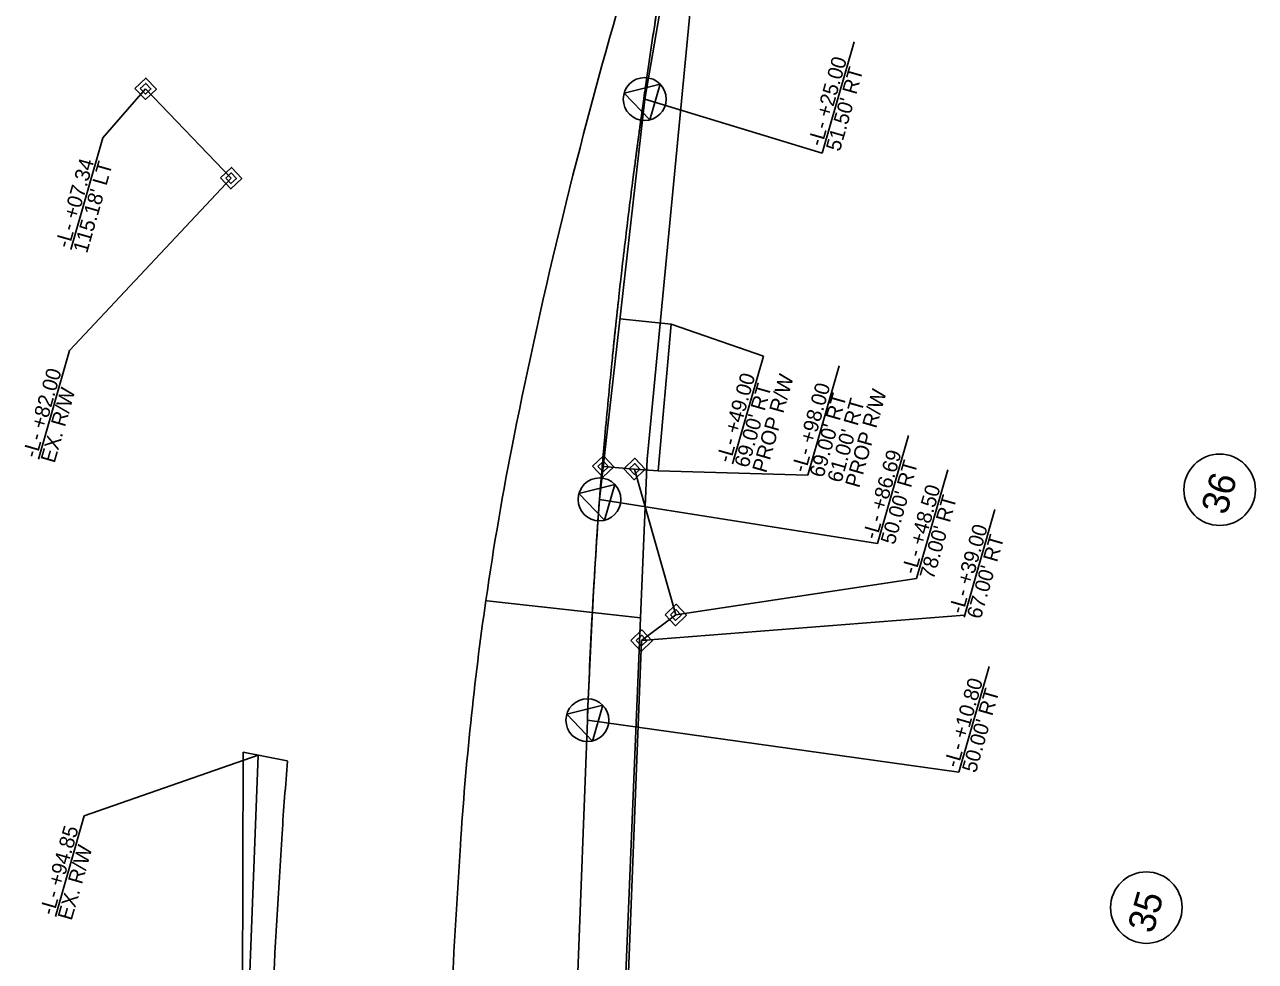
# Model space of a CAD drawing. Extents: x 2097272 to 2098144, y 685104 to 689282.
# Drawn here: x 2097646.2 to 2098059.6, y 688445.5 to 688760 of the extents above; entities that cross this region are included whole.
import ezdxf

# ---------------------------------------------------------------- set-up
doc = ezdxf.new("R2010")
doc.units = 0
for name, color, linetype in [('Prop Easement Construction', 7, 'Continuous'), ('Prop Easement Construction Station Offsets', 7, 'Continuous'), ('Prop Easement Permanent Utility', 7, 'Continuous'), ('Prop Easement Permanent Utility Station Offsets', 7, 'Continuous'), ('Prop Parcel Number CELL', 7, 'Continuous'), ('Prop ROW Marker CELL', 7, 'Continuous'), ('Prop ROW Permanent Easement CELL', 7, 'Continuous'), ('Prop ROW RW Lines', 7, 'Continuous'), ('Prop ROW Station Offsets', 7, 'Continuous'), ('Scratch_Level_3', 7, 'Continuous'), ('Scratch_Level_6', 7, 'Continuous')]:
    doc.layers.add(name, color=color, linetype=linetype)

msp = doc.modelspace()

# ---------------------------------------------------------------- linework, layer by layer
at = {"layer": 'Prop Easement Construction'}
for p, q in [((2097863.36, 688659.46), (2097846.12, 688661.16)), ((2097859.04, 688610.18), (2097863.36, 688659.46)), ((2097859.04, 688610.18), (2097851.06, 688610.79)), ((2097719.27, 688373.62), (2097724.68, 688514.75))]:
    msp.add_line(p, q, dxfattribs=at)
at = {"layer": 'Prop Easement Construction Station Offsets'}
for p, q in [((2097894.32, 688648.68), (2097863.36, 688659.46)), ((2097894.32, 688648.68), (2097883.97, 688612.54)), ((2097666.26, 688494.4), (2097724.68, 688514.75)), ((2097656.57, 688460.53), (2097666.26, 688494.4))]:
    msp.add_line(p, q, dxfattribs=at)
at = {"layer": 'Prop Easement Permanent Utility'}
for p, q in [((2097715.56, 688708.41), (2097686.86, 688738.44)), ((2097715.61, 688708.41), (2097715.5, 688708.42)), ((2097851.06, 688610.79), (2097840.52, 688611.6)), ((2097864.89, 688561.78), (2097851.06, 688610.79)), ((2097853.42, 688553.17), (2097864.89, 688561.78)), ((2097846.96, 688389.12), (2097853.42, 688553.17))]:
    msp.add_line(p, q, dxfattribs=at)
at = {"layer": 'Prop Easement Permanent Utility Station Offsets'}
for p, q in [((2097672.48, 688721.94), (2097686.86, 688738.44)), ((2097661.77, 688684.52), (2097672.48, 688721.94)), ((2097661.32, 688650.61), (2097715.56, 688708.41)), ((2097650.86, 688614.08), (2097661.32, 688650.61)), ((2097919.8, 688645.37), (2097909.3, 688608.7)), ((2097909.3, 688608.7), (2097859.04, 688610.18)), ((2097956.22, 688610.51), (2097945.76, 688573.98)), ((2097972.08, 688597.22), (2097961.73, 688561.08)), ((2097945.76, 688573.98), (2097864.89, 688561.78)), ((2097961.92, 688561.71), (2097853.42, 688553.17))]:
    msp.add_line(p, q, dxfattribs=at)
at = {"layer": 'Prop Parcel Number CELL'}
for centre in [(2098047.57, 688603.82), (2098022.94, 688463.54)]:
    msp.add_circle(centre, 12, dxfattribs=at)
at = {"layer": 'Prop ROW Marker CELL'}
for p, q in [((2097686.86, 688738.44), (2097686.86, 688738.44)), ((2097854.46, 688734.99), (2097854.46, 688734.99)), ((2097715.56, 688708.41), (2097715.56, 688708.41)), ((2097840.52, 688611.6), (2097840.52, 688611.6)), ((2097851.06, 688610.79), (2097851.06, 688610.79)), ((2097839.28, 688600.59), (2097839.28, 688600.59)), ((2097864.89, 688561.78), (2097864.89, 688561.78)), ((2097853.42, 688553.17), (2097853.42, 688553.17)), ((2097835.21, 688526.47), (2097835.21, 688526.47))]:
    msp.add_line(p, q, dxfattribs=at)
for points in [[(2097856.2, 688727.99), (2097847.54, 688736.97), (2097859.64, 688740)], [(2097841.02, 688593.59), (2097832.36, 688602.58), (2097844.46, 688605.61)], [(2097836.95, 688519.47), (2097828.29, 688528.45), (2097840.39, 688531.49)]]:
    msp.add_lwpolyline(points, close=True, dxfattribs=at)
for centre in [(2097854.46, 688734.99), (2097839.28, 688600.59), (2097835.21, 688526.47)]:
    msp.add_circle(centre, 7.2, dxfattribs=at)
at = {"layer": 'Prop ROW Permanent Easement CELL'}
for points in [[(2097683.26, 688738.54), (2097686.97, 688742.04), (2097690.46, 688738.33), (2097686.76, 688734.84)], [(2097685.06, 688738.49), (2097686.91, 688740.24), (2097688.66, 688738.38), (2097686.81, 688736.64)], [(2097711.96, 688708.52), (2097715.67, 688712.01), (2097719.16, 688708.31), (2097715.46, 688704.81)], [(2097713.76, 688708.47), (2097715.62, 688710.21), (2097717.36, 688708.36), (2097715.51, 688706.61)], [(2097836.92, 688611.7), (2097840.63, 688615.19), (2097844.12, 688611.49), (2097840.42, 688608)], [(2097838.72, 688611.65), (2097840.58, 688613.4), (2097842.32, 688611.54), (2097840.47, 688609.8)], [(2097847.47, 688610.9), (2097851.17, 688614.39), (2097854.66, 688610.69), (2097850.96, 688607.19)], [(2097849.26, 688610.84), (2097851.12, 688612.59), (2097852.86, 688610.74), (2097851.01, 688608.99)], [(2097861.29, 688561.88), (2097864.99, 688565.38), (2097868.48, 688561.67), (2097864.78, 688558.18)], [(2097863.09, 688561.83), (2097864.94, 688563.58), (2097866.68, 688561.73), (2097864.83, 688559.98)], [(2097849.82, 688553.27), (2097853.52, 688556.77), (2097857.01, 688553.06), (2097853.31, 688549.57)], [(2097851.62, 688553.22), (2097853.47, 688554.97), (2097855.22, 688553.12), (2097853.36, 688551.37)]]:
    msp.add_lwpolyline(points, close=True, dxfattribs=at)
at = {"layer": 'Prop ROW RW Lines'}
for p, q in [((2097854.46, 688734.99), (2097881.38, 688888.89)), ((2097839.28, 688600.59), (2097854.46, 688734.99)), ((2097823.42, 688219.05), (2097835.21, 688526.47))]:
    msp.add_line(p, q, dxfattribs=at)
msp.add_arc((2100083.56, 688440.25), 2250, 175.9133, 177.8037, dxfattribs=at)
at = {"layer": 'Prop ROW Station Offsets'}
for p, q in [((2097924.77, 688754.2), (2097914.07, 688716.83)), ((2097914.07, 688716.83), (2097854.46, 688734.99)), ((2097943.1, 688622.08), (2097932.7, 688585.75)), ((2097932.7, 688585.75), (2097839.28, 688600.59)), ((2097970.13, 688544.45), (2097960, 688509.06)), ((2097960, 688509.06), (2097835.21, 688526.47))]:
    msp.add_line(p, q, dxfattribs=at)
at = {"layer": 'Scratch_Level_3'}
for p, q in [((2097801.12, 688566.59), (2097801.56, 688566.55)), ((2097801.56, 688566.55), (2097801.12, 688566.59)), ((2097801.56, 688566.55), (2097836.89, 688562.64)), ((2097836.89, 688562.64), (2097801.56, 688566.55)), ((2097829.17, 688369.06), (2097835.21, 688526.47))]:
    msp.add_line(p, q, dxfattribs=at)
msp.add_lwpolyline([(2097839.28, 688600.59), (2097839.28, 688600.59)], dxfattribs=at)
for centre, radius, start, end in [((2099533.7, 688278.93), 1756.88, 163.79986, 168.76087), ((2098839.67, 688416.84), 1049.29, 168.76087, 171.79497), ((2100083.56, 688440.25), 2250, 175.9133, 176.88183), ((2100083.56, 688440.25), 2250, 175.913298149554, 175.91330221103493), ((2098839.67, 688416.84), 1049.29, 171.79497, 176.30351), ((2100083.56, 688440.25), 2250, 176.88183, 177.8037), ((2101879.05, 688220.48), 4095, 176.30351, 177.90917)]:
    msp.add_arc(centre, radius, start, end, dxfattribs=at)
for points, degree in [([(2097852.36, 688722), (2097852.38, 688722.16), (2097852.4, 688722.32), (2097852.45, 688722.63), (2097852.47, 688722.79), (2097852.51, 688723.1), (2097852.53, 688723.26), (2097852.56, 688723.46), (2097852.56, 688723.5), (2097852.58, 688723.58), (2097852.58, 688723.62), (2097852.6, 688723.74), (2097852.61, 688723.82), (2097852.7, 688724.53), (2097852.79, 688725.16), (2097853.05, 688727.05), (2097853.22, 688728.31), (2097853.75, 688732.09), (2097854.81, 688739.65), (2097856.65, 688752.25), (2097858.57, 688764.83), (2097859.76, 688772.38), (2097860.36, 688776.15), (2097860.56, 688777.41), (2097860.86, 688779.29), (2097860.97, 688779.92), (2097861.08, 688780.63), (2097861.09, 688780.71), (2097861.11, 688780.8), (2097861.11, 688780.82), (2097861.12, 688780.86), (2097861.12, 688780.88), (2097861.13, 688780.94), (2097861.14, 688780.98), (2097861.17, 688781.18), (2097861.2, 688781.33), (2097861.25, 688781.65), (2097861.27, 688781.81), (2097861.32, 688782.12), (2097861.35, 688782.28), (2097861.38, 688782.44)], 3), ([(2097844.99, 688661.33), (2097845.01, 688661.49), (2097845.02, 688661.64), (2097845.06, 688661.96), (2097845.08, 688662.12), (2097845.11, 688662.43), (2097845.13, 688662.59), (2097845.15, 688662.79), (2097845.15, 688662.83), (2097845.16, 688662.91), (2097845.17, 688662.95), (2097845.18, 688663.07), (2097845.19, 688663.15), (2097845.26, 688663.86), (2097845.33, 688664.49), (2097845.54, 688666.39), (2097845.68, 688667.66), (2097846.1, 688671.45), (2097846.96, 688679.05), (2097848.45, 688691.69), (2097850.03, 688704.32), (2097851.02, 688711.9), (2097851.52, 688715.69), (2097851.68, 688716.95), (2097851.94, 688718.84), (2097852.02, 688719.47), (2097852.12, 688720.18), (2097852.13, 688720.26), (2097852.14, 688720.36), (2097852.14, 688720.38), (2097852.15, 688720.42), (2097852.15, 688720.44), (2097852.16, 688720.5), (2097852.16, 688720.54), (2097852.19, 688720.73), (2097852.21, 688720.89), (2097852.25, 688721.21), (2097852.28, 688721.37), (2097852.32, 688721.68), (2097852.34, 688721.84), (2097852.36, 688722)], 3), ([(2097839.28, 688600.59), (2097839.28, 688600.61), (2097839.29, 688600.66), (2097839.29, 688600.78), (2097839.3, 688600.85), (2097839.32, 688601.09), (2097839.33, 688601.25), (2097839.36, 688601.57), (2097839.37, 688601.73), (2097839.39, 688601.93), (2097839.39, 688601.97), (2097839.4, 688602.03), (2097839.4, 688602.05), (2097839.4, 688602.09), (2097839.4, 688602.11), (2097839.41, 688602.21), (2097839.42, 688602.28), (2097839.48, 688603), (2097839.53, 688603.63), (2097839.68, 688605.54), (2097839.79, 688606.81), (2097840.11, 688610.61), (2097840.76, 688618.23), (2097841.91, 688630.91), (2097843.14, 688643.59), (2097843.92, 688651.19), (2097844.32, 688654.99), (2097844.45, 688656.26), (2097844.65, 688658.16), (2097844.72, 688658.79), (2097844.79, 688659.5), (2097844.8, 688659.58), (2097844.81, 688659.68), (2097844.82, 688659.7), (2097844.82, 688659.74), (2097844.82, 688659.76), (2097844.83, 688659.82), (2097844.83, 688659.86), (2097844.85, 688660.06), (2097844.87, 688660.21), (2097844.9, 688660.53), (2097844.92, 688660.69), (2097844.96, 688661.01), (2097844.97, 688661.17), (2097844.99, 688661.33)], 3), ([(2097839.28, 688600.59), (2097839.28, 688600.59), (2097839.28, 688600.59), (2097839.28, 688600.59)], 2)]:
    msp.add_open_spline(points, degree=degree, dxfattribs=at)
at = {"layer": 'Scratch_Level_6'}
for p, q in [((2097855.33, 688614.06), (2097873.91, 688807.74)), ((2097853.1, 688560.84), (2097855.33, 688614.06)), ((2097836.89, 688562.64), (2097853.1, 688560.84)), ((2097853.1, 688560.84), (2097836.89, 688562.64)), ((2097845.06, 688368.79), (2097853.1, 688560.84)), ((2097835.21, 688526.47), (2097829.17, 688369.06)), ((2097719.57, 688515.78), (2097719.2, 688371.69)), ((2097734.39, 688512.78), (2097719.57, 688515.78)), ((2097734.54, 688512.75), (2097734.39, 688512.78))]:
    msp.add_line(p, q, dxfattribs=at)
for centre, radius, start, end in [((2100083.56, 688440.25), 2250, 175.9133, 176.88183), ((2100083.56, 688440.25), 2250, 176.88183, 177.8037), ((2098839.67, 688416.84), 1109.29, 175.0401, 176.30351), ((2101879.05, 688220.48), 4155, 176.30351, 177.90917)]:
    msp.add_arc(centre, radius, start, end, dxfattribs=at)
for points, degree in [([(2097860.16, 688774.89), (2097859.76, 688772.38), (2097858.57, 688764.83), (2097856.65, 688752.25), (2097854.81, 688739.65), (2097853.75, 688732.09), (2097853.22, 688728.31), (2097853.05, 688727.05), (2097852.79, 688725.16), (2097852.7, 688724.53), (2097852.61, 688723.82), (2097852.6, 688723.74), (2097852.58, 688723.62), (2097852.58, 688723.58), (2097852.56, 688723.5), (2097852.56, 688723.46), (2097852.53, 688723.26), (2097852.51, 688723.1), (2097852.47, 688722.79), (2097852.45, 688722.63), (2097852.42, 688722.42), (2097852.41, 688722.37), (2097852.4, 688722.32)], 3), ([(2097852.14, 688720.36), (2097852.14, 688720.35), (2097852.14, 688720.35), (2097852.13, 688720.26), (2097852.12, 688720.18), (2097852.02, 688719.47), (2097851.94, 688718.84), (2097851.85, 688718.21)], 3), ([(2097852.15, 688720.46), (2097852.15, 688720.46), (2097852.15, 688720.46), (2097852.15, 688720.44), (2097852.15, 688720.42), (2097852.14, 688720.39), (2097852.14, 688720.37), (2097852.14, 688720.36)], 3), ([(2097852.17, 688720.58), (2097852.17, 688720.58), (2097852.17, 688720.58), (2097852.16, 688720.54), (2097852.16, 688720.5), (2097852.15, 688720.46)], 3), ([(2097852.3, 688721.53), (2097852.28, 688721.37), (2097852.25, 688721.21), (2097852.21, 688720.89), (2097852.19, 688720.74), (2097852.17, 688720.58)], 3), ([(2097852.36, 688722), (2097852.34, 688721.84), (2097852.32, 688721.68), (2097852.3, 688721.53)], 2), ([(2097852.4, 688722.32), (2097852.39, 688722.21), (2097852.38, 688722.11), (2097852.36, 688722)], 2), ([(2097851.63, 688716.57), (2097851.54, 688715.86), (2097851.44, 688715.14), (2097851.02, 688711.9), (2097850.03, 688704.32), (2097848.45, 688691.69), (2097846.96, 688679.05), (2097846.1, 688671.45), (2097845.68, 688667.66), (2097845.54, 688666.39), (2097845.33, 688664.49), (2097845.26, 688663.86), (2097845.19, 688663.15), (2097845.18, 688663.07), (2097845.17, 688662.95), (2097845.16, 688662.91), (2097845.15, 688662.83), (2097845.15, 688662.79), (2097845.14, 688662.7), (2097845.13, 688662.65), (2097845.13, 688662.59)], 3), ([(2097851.85, 688718.21), (2097851.85, 688718.21), (2097851.85, 688718.21), (2097851.78, 688717.67), (2097851.71, 688717.12), (2097851.63, 688716.57)], 3), ([(2097844.99, 688661.33), (2097844.97, 688661.17), (2097844.96, 688661.01), (2097844.92, 688660.69), (2097844.9, 688660.53), (2097844.87, 688660.21), (2097844.85, 688660.06), (2097844.83, 688659.86), (2097844.83, 688659.82), (2097844.82, 688659.78), (2097844.82, 688659.78), (2097844.82, 688659.78)], 3), ([(2097845.13, 688662.59), (2097845.12, 688662.49), (2097845.1, 688662.38), (2097845.08, 688662.12), (2097845.06, 688661.96), (2097845.02, 688661.64), (2097845.01, 688661.49), (2097844.99, 688661.33)], 3), ([(2097844.79, 688659.5), (2097844.79, 688659.48), (2097844.79, 688659.45), (2097844.72, 688658.79), (2097844.65, 688658.16), (2097844.47, 688656.44), (2097844.36, 688655.36), (2097844.24, 688654.28)], 3), ([(2097844.82, 688659.72), (2097844.82, 688659.72), (2097844.82, 688659.72), (2097844.82, 688659.7), (2097844.81, 688659.68), (2097844.81, 688659.61), (2097844.8, 688659.56), (2097844.79, 688659.5)], 3), ([(2097844.82, 688659.78), (2097844.82, 688659.76), (2097844.82, 688659.74), (2097844.82, 688659.72)], 2), ([(2097844.24, 688654.28), (2097844.22, 688654.1), (2097844.2, 688653.91), (2097843.92, 688651.19), (2097843.14, 688643.59), (2097841.91, 688630.91), (2097840.76, 688618.23), (2097840.11, 688610.61), (2097839.8, 688606.92), (2097839.7, 688605.75), (2097839.61, 688604.59)], 3), ([(2097839.54, 688603.77), (2097839.5, 688603.3), (2097839.46, 688602.83), (2097839.42, 688602.28), (2097839.41, 688602.21), (2097839.4, 688602.11), (2097839.4, 688602.1), (2097839.4, 688602.09)], 3), ([(2097839.61, 688604.59), (2097839.6, 688604.48), (2097839.59, 688604.38), (2097839.57, 688604.1), (2097839.55, 688603.93), (2097839.54, 688603.77)], 3), ([(2097839.37, 688601.73), (2097839.36, 688601.62), (2097839.35, 688601.52), (2097839.33, 688601.25), (2097839.32, 688601.09), (2097839.3, 688600.85), (2097839.29, 688600.78), (2097839.29, 688600.66), (2097839.28, 688600.61), (2097839.28, 688600.59)], 3), ([(2097839.4, 688602.09), (2097839.4, 688602.08), (2097839.4, 688602.07), (2097839.4, 688602.05), (2097839.4, 688602.03), (2097839.39, 688601.97), (2097839.39, 688601.93), (2097839.38, 688601.83), (2097839.38, 688601.78), (2097839.37, 688601.73)], 3)]:
    msp.add_open_spline(points, degree=degree, dxfattribs=at)

# ---------------------------------------------------------------- texts
at = {"layer": 'Prop Easement Construction Station Offsets'}
for s, p in [('-L- +49.00', (2097883.24, 688612.64)), ('PROP R/W', (2097895.26, 688609.2)), ("69.00' RT", (2097889.25, 688610.92)), ('-L- +94.85', (2097655.97, 688460.7)), ('EX. R/W', (2097661.98, 688458.98))]:
    msp.add_text(s, height=5, rotation=74.0259, dxfattribs=at).set_placement(p)
at = {"layer": 'Prop Easement Permanent Utility Station Offsets'}
for s, p in [('-L- +07.34', (2097661.17, 688684.7)), ("115.18' LT", (2097667.18, 688682.98)), ('-L- +82.00', (2097650.26, 688614.25)), ('EX. R/W', (2097656.27, 688612.53)), ('-L- +98.00', (2097908.46, 688609.35)), ("69.00' RT", (2097914.46, 688607.63)), ('PROP R/W', (2097926.48, 688604.19)), ("61.00' RT", (2097920.47, 688605.91)), ('-L- +48.50', (2097945.45, 688575.17)), ("78.00' RT", (2097951.46, 688573.45)), ('-L- +39.00', (2097961.31, 688561.88)), ("67.00' RT", (2097967.32, 688560.16))]:
    msp.add_text(s, height=5, rotation=74.0259, dxfattribs=at).set_placement(p)
at = {"layer": 'Prop Parcel Number CELL'}
for s, p in [('36', (2098049.83, 688595.04)), ('35', (2098025.14, 688454.52))]:
    msp.add_text(s, height=9, rotation=74.0259, dxfattribs=at).set_placement(p)
at = {"layer": 'Prop ROW Station Offsets'}
for s, p in [('-L- +25.00', (2097914, 688718.86)), ("51.50' RT", (2097920.01, 688717.14)), ('-L- +86.69', (2097932.37, 688586.86)), ("50.00' RT", (2097938.38, 688585.14)), ('-L- +10.80', (2097959.69, 688510.26)), ("50.00' RT", (2097965.7, 688508.54))]:
    msp.add_text(s, height=5, rotation=74.0259, dxfattribs=at).set_placement(p)

doc.saveas('drawing.dxf')
